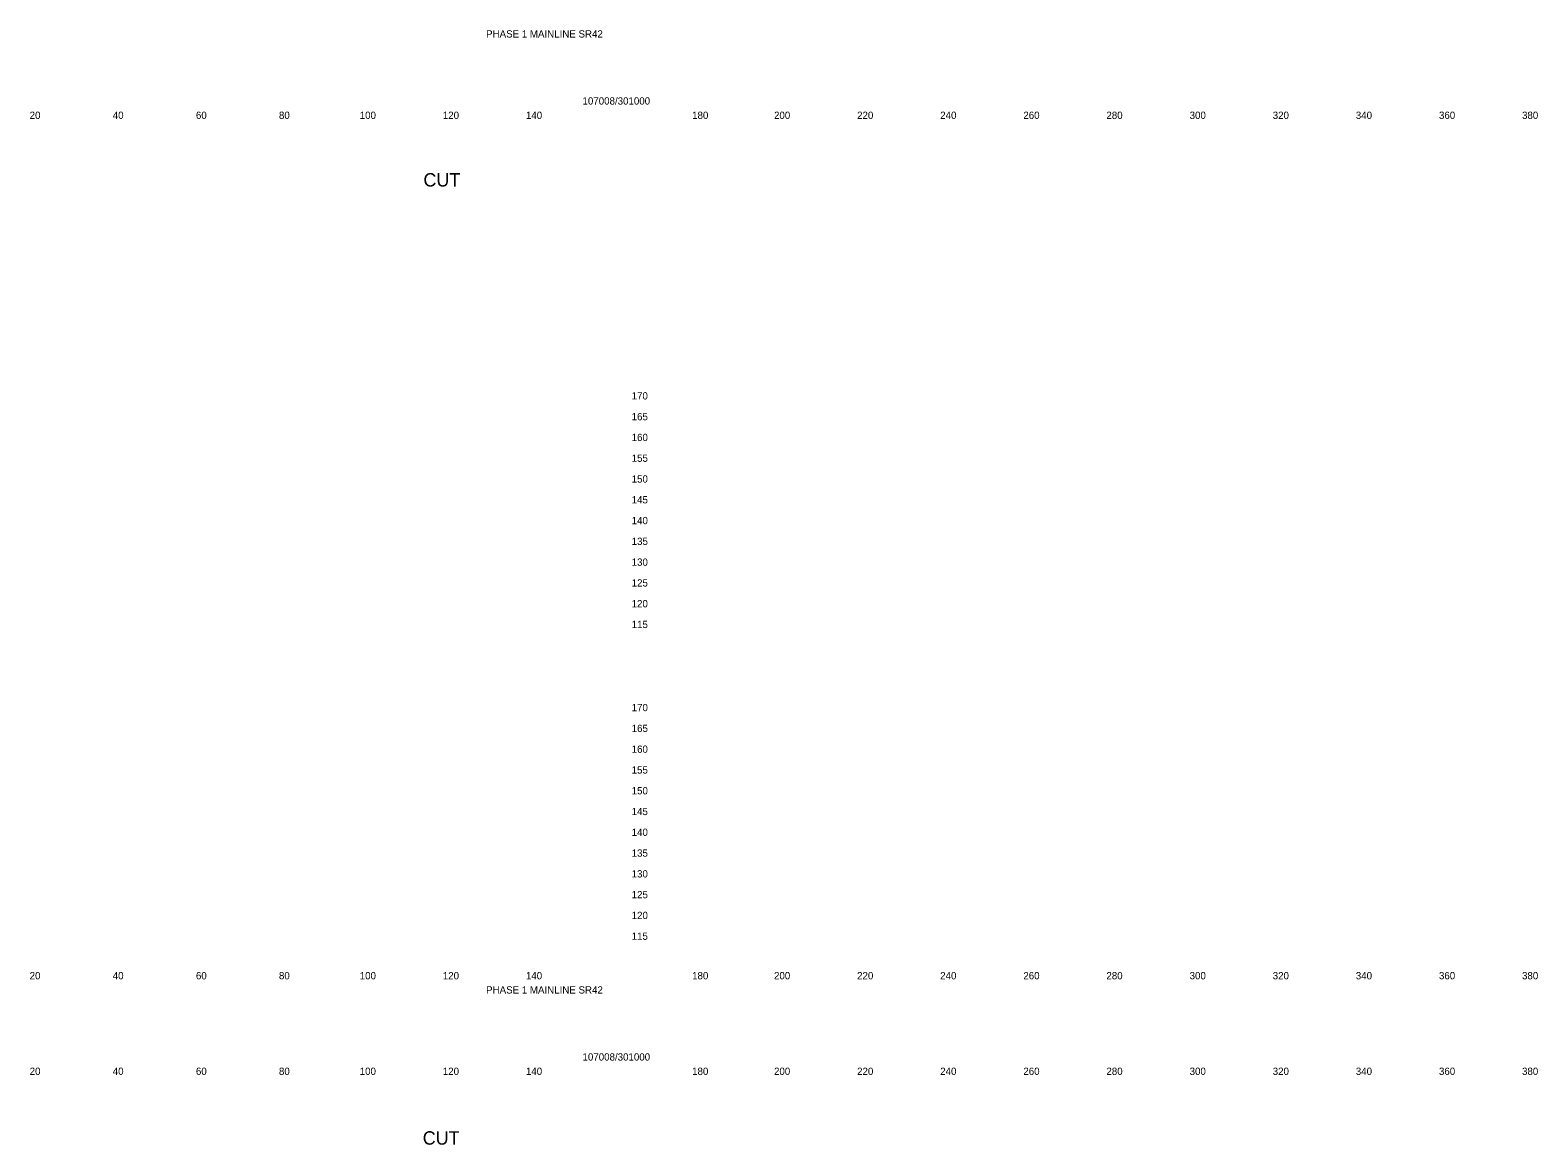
# Model space of a CAD drawing. Extents: x 21281 to 22024, y 6472 to 15198.
# Drawn here: x 21661.4 to 22024.2, y 13565.5 to 13833.7 of the extents above; entities that cross this region are included whole.
import ezdxf

# ---------------------------------------------------------------- set-up
doc = ezdxf.new("R2010")
doc.units = 0
doc.layers.add('XS_SHEET_LABELS_ELEVATION', color=7, linetype='Continuous')
doc.layers.add('XS_SHEET_LABELS_OFFSET', color=7, linetype='Continuous')

msp = doc.modelspace()

# ---------------------------------------------------------------- texts
at = {"layer": 'XS_SHEET_LABELS_ELEVATION'}
for s, p in [('  170  ', (21804.84, 13744.84)), ('  165  ', (21804.84, 13739.84)), ('  160  ', (21804.84, 13734.84)), ('  155  ', (21804.84, 13729.84)), ('  150  ', (21804.84, 13724.84)), ('  145  ', (21804.84, 13719.84)), ('  140  ', (21804.84, 13714.84)), ('  135  ', (21804.84, 13709.84)), ('  130  ', (21804.84, 13704.84)), ('  125  ', (21804.84, 13699.84)), ('  120  ', (21804.84, 13694.84)), ('  115  ', (21804.84, 13689.84)), ('  170  ', (21804.84, 13669.84)), ('  165  ', (21804.84, 13664.84)), ('  160  ', (21804.84, 13659.84)), ('  155  ', (21804.84, 13654.84)), ('  150  ', (21804.84, 13649.84)), ('  145  ', (21804.84, 13644.84)), ('  140  ', (21804.84, 13639.84)), ('  135  ', (21804.84, 13634.84)), ('  130  ', (21804.84, 13629.84)), ('  125  ', (21804.84, 13624.84)), ('  120  ', (21804.84, 13619.84)), ('  115  ', (21804.84, 13614.84))]:
    msp.add_text(s, height=1.75, dxfattribs=at).set_placement(p)
at = {"layer": 'XS_SHEET_LABELS_OFFSET'}
for s, height, p in [('PHASE 1 MAINLINE SR42', 1.75, (21771.11, 13831.92)), ('107008/301000', 1.75, (21794.31, 13815.79)), ('  20  ', 1.75, (21659.95, 13812.34)), ('  40  ', 1.75, (21679.95, 13812.34)), ('  60  ', 1.75, (21699.97, 13812.34)), ('  80  ', 1.75, (21719.95, 13812.34)), ('  100  ', 1.75, (21739.39, 13812.34)), ('  120  ', 1.75, (21759.39, 13812.34)), ('  140  ', 1.75, (21779.39, 13812.34)), ('  180  ', 1.75, (21819.39, 13812.34)), ('  200  ', 1.75, (21839.1, 13812.34)), ('  220  ', 1.75, (21859.1, 13812.34)), ('  240  ', 1.75, (21879.1, 13812.34)), ('  260  ', 1.75, (21899.11, 13812.34)), ('  280  ', 1.75, (21919.1, 13812.34)), ('  300  ', 1.75, (21939.13, 13812.34)), ('  320  ', 1.75, (21959.13, 13812.34)), ('  340  ', 1.75, (21979.13, 13812.34)), ('  360  ', 1.75, (21999.14, 13812.34)), ('  380  ', 1.75, (22019.13, 13812.34)), ('CUT', 3.222, (21756.03, 13796.07)), ('  20  ', 1.75, (21659.95, 13605.34)), ('  40  ', 1.75, (21679.95, 13605.34)), ('  60  ', 1.75, (21699.97, 13605.34)), ('  80  ', 1.75, (21719.95, 13605.34)), ('  100  ', 1.75, (21739.39, 13605.34)), ('  120  ', 1.75, (21759.39, 13605.34)), ('  140  ', 1.75, (21779.39, 13605.34)), ('  180  ', 1.75, (21819.39, 13605.34)), ('  200  ', 1.75, (21839.1, 13605.34)), ('  220  ', 1.75, (21859.1, 13605.34)), ('  240  ', 1.75, (21879.1, 13605.34)), ('  260  ', 1.75, (21899.11, 13605.34)), ('  280  ', 1.75, (21919.1, 13605.34)), ('  300  ', 1.75, (21939.13, 13605.34)), ('  320  ', 1.75, (21959.13, 13605.34)), ('  340  ', 1.75, (21979.13, 13605.34)), ('  360  ', 1.75, (21999.14, 13605.34)), ('  380  ', 1.75, (22019.13, 13605.34)), ('PHASE 1 MAINLINE SR42', 1.75, (21771.11, 13601.92)), ('107008/301000', 1.75, (21794.31, 13585.79)), ('  20  ', 1.75, (21659.95, 13582.34)), ('  40  ', 1.75, (21679.95, 13582.34)), ('  60  ', 1.75, (21699.97, 13582.34)), ('  80  ', 1.75, (21719.95, 13582.34)), ('  100  ', 1.75, (21739.39, 13582.34)), ('  120  ', 1.75, (21759.39, 13582.34)), ('  140  ', 1.75, (21779.39, 13582.34)), ('  180  ', 1.75, (21819.39, 13582.34)), ('  200  ', 1.75, (21839.1, 13582.34)), ('  220  ', 1.75, (21859.1, 13582.34)), ('  240  ', 1.75, (21879.1, 13582.34)), ('  260  ', 1.75, (21899.11, 13582.34)), ('  280  ', 1.75, (21919.1, 13582.34)), ('  300  ', 1.75, (21939.13, 13582.34)), ('  320  ', 1.75, (21959.13, 13582.34)), ('  340  ', 1.75, (21979.13, 13582.34)), ('  360  ', 1.75, (21999.14, 13582.34)), ('  380  ', 1.75, (22019.13, 13582.34)), ('CUT', 3.222, (21755.86, 13565.56))]:
    msp.add_text(s, height=height, dxfattribs=at).set_placement(p)

doc.saveas('drawing.dxf')
